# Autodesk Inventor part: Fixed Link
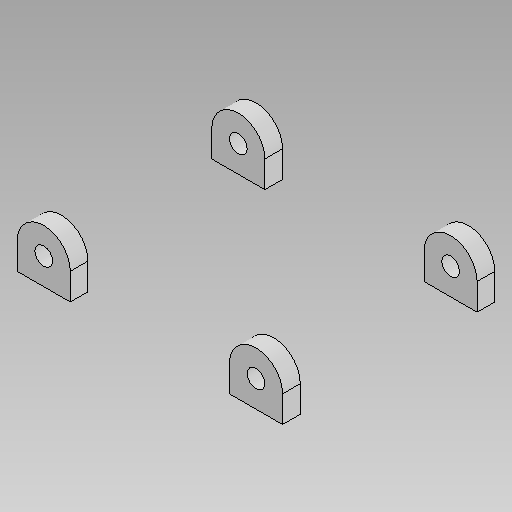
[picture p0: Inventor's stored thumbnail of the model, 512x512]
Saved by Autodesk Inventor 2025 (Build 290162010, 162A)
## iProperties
Created: 2024-10
Part Number: Fixed Link
Material: Generic
Document SubType Name: Modeling
Designer: Dennis
Mass: 3.62445 g
Surface Area: 28.3518 cm^2
Volume: 3.62445 cm^3
Density: 1 g/cm^3
Appearance: Default
Author: Dennis
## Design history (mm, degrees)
sketch "Sketch1"
  geometry: L1 (22.5, -25)-(37.5, -25); L2 (37.5, -25)-(37.5, -30); L3 (37.5, -30)-(22.5, -30); L4 (22.5, -30)-(22.5, -25); L5 (22.5, -25)-(37.5, -30); L6 (37.5, -25)-(22.5, -30); L7 (0, -42)-(0, 42) reference; L8 (-52.5, 0)-(52.5, 0) reference; L9 (-22.5, -25)-(-37.5, -25); L10 (-37.5, -25)-(-37.5, -30); L11 (-37.5, -30)-(-22.5, -30); L12 (-22.5, -30)-(-22.5, -25); L13 (-22.5, -25)-(-37.5, -30); L14 (-37.5, -25)-(-22.5, -30); L15 (-22.5, 30)-(-37.5, 30); L16 (-37.5, 30)-(-37.5, 25); L17 (-37.5, 25)-(-22.5, 25); L18 (-22.5, 25)-(-22.5, 30); L19 (-22.5, 30)-(-37.5, 25); L20 (-37.5, 30)-(-22.5, 25); L21 (22.5, 30)-(37.5, 30); L22 (37.5, 30)-(37.5, 25); L23 (37.5, 25)-(22.5, 25); L24 (22.5, 25)-(22.5, 30); L25 (22.5, 30)-(37.5, 25); L26 (37.5, 30)-(22.5, 25); 5 further points
  constraints: 48 end point, 8 midpoint, 8 parallel, 6 equal length, 4 horizontal, 4 perpendicular, 2 point on line, 2 symmetric about line
  dimensions: "d0" = 15 distance of L2.end L3.end; "d1" = 5 distance of L1.end L2.end; "d2" = 27.5 distance from line of L8 point (30, -27.5); "d3" = 30 distance from line of L7 point (30, -27.5)
extrude "Extrusion1" new body sketch "Sketch1" distance "d4" = 15; taper "d5" = 0 deg
fillet "Fillet1" dims "d6" = 7.5 (= 0.5 x d0)
sketch "Sketch2"
  geometry: A1 r 7.5 centre (7.5, 7.5) between (15, 7.5) and (0, 7.5) reference; A2 r 7.5 centre (67.5, 7.5) between (75, 7.5) and (60, 7.5) reference; 3 further points
  constraints: 2 coincident
hole "Hole1" sketch "Sketch2" at (7.5, 7.5), (67.5, 7.5) diameter "d7" = 5; stored, may be unused: countersink angle "d11" = 90 deg, drill point angle "d13" = 118 deg; dims "d8" = 6, "d9" = 8, "d10" = 4.6, "d12" = 8
body "Solid1"
